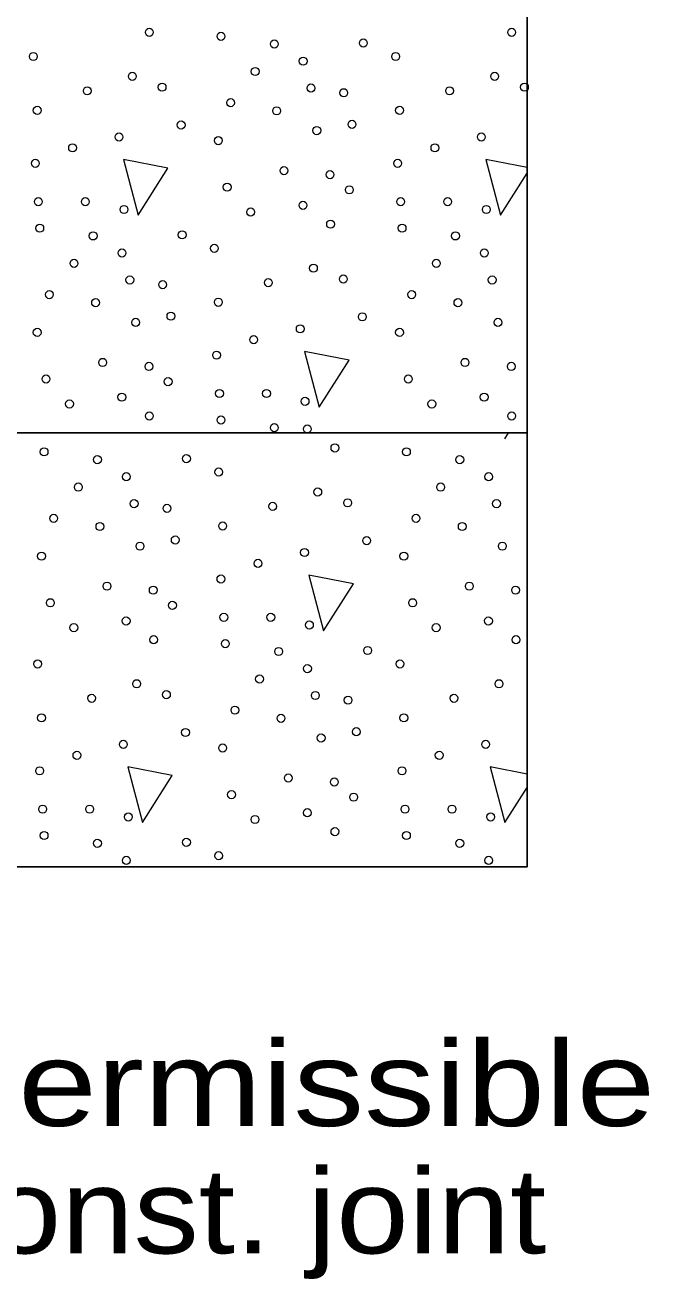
# Model space of a CAD drawing. Extents: x -410.5 to -376.5, y 1617.6 to 1661.6.
# Drawn here: x -391.077 to -389.927, y 1629.387 to 1631.696 of the extents above; entities that cross this region are included whole.
import ezdxf

# ---------------------------------------------------------------- set-up
doc = ezdxf.new("R2010")
doc.units = 0
doc.header["$LTSCALE"] = 0.062
doc.layers.add('1', color=7, linetype='Continuous', lineweight=13)

msp = doc.modelspace()

# ---------------------------------------------------------------- linework, layer by layer
at = {"layer": '1'}
for p, q in [((-390.22783, 1631.44833), (-390.20083, 1631.34592)), ((-390.15158, 1631.4335), (-390.22783, 1631.44833)), ((-390.20083, 1631.34592), (-390.15158, 1631.42333)), ((-390.19292, 1630.93383), (-390.18583, 1630.94508)), ((-390.21983, 1630.3295), (-390.19292, 1630.22717)), ((-390.15175, 1630.31625), (-390.21983, 1630.3295)), ((-390.19292, 1630.22717), (-390.15167, 1630.29192))]:
    msp.add_line(p, q, dxfattribs=at)
at = {"layer": '1', "lineweight": 25}
for points in [[(-391.09567, 1634.05167), (-391.07275, 1634.05717), (-390.86258, 1634.005), (-390.75258, 1634.02892), (-390.70333, 1634.03392), (-390.53658, 1634.02533), (-390.38608, 1633.99358), (-390.15167, 1634.0215), (-390.15167, 1630.94508), (-391.09567, 1630.94508)], [(-395.15925, 1630.79517), (-394.77725, 1630.79517), (-394.77725, 1630.1455), (-390.15167, 1630.1455), (-390.15167, 1630.94508), (-394.16367, 1630.94508), (-394.16367, 1630.79517), (-393.83325, 1630.79517), (-393.83325, 1630.64525), (-394.27908, 1630.64525), (-394.54583, 1630.79517), (-394.77725, 1630.79517)]]:
    msp.add_lwpolyline(points, dxfattribs=at)
at = {"layer": '1'}
for points in [[(-390.89542, 1631.44833), (-390.86842, 1631.34592), (-390.81342, 1631.43233)], [(-390.56158, 1631.095), (-390.53458, 1630.9925), (-390.47967, 1631.079)], [(-390.55358, 1630.68292), (-390.52667, 1630.58042), (-390.47167, 1630.66692)], [(-390.88733, 1630.3295), (-390.86033, 1630.22717), (-390.8055, 1630.31358)]]:
    msp.add_lwpolyline(points, close=True, dxfattribs=at)
for centre, major_axis in [((-390.8475, 1631.68266), (0, -0.00756)), ((-390.18, 1631.68266), (0, -0.00756)), ((-390.71567, 1631.67536), (0, -0.00756)), ((-390.61738, 1631.66105), (0, 0.00756)), ((-390.4534, 1631.66293), (0, -0.00756)), ((-391.06144, 1631.63814), (0, -0.00756)), ((-390.39393, 1631.63814), (0, -0.00756)), ((-390.65259, 1631.61046), (0, 0.00756)), ((-390.56426, 1631.62954), (0, 0.00756)), ((-390.87904, 1631.60157), (0, -0.00756)), ((-390.21154, 1631.60157), (0, -0.00756)), ((-390.96198, 1631.57489), (0, -0.00756)), ((-390.82409, 1631.58154), (0, -0.00756)), ((-390.5498, 1631.57995), (0, 0.00756)), ((-390.48944, 1631.5713), (0, -0.00756)), ((-390.29447, 1631.57489), (0, -0.00756)), ((-390.15658, 1631.58154), (0, -0.00756)), ((-390.69793, 1631.55292), (0, 0.00756)), ((-391.05421, 1631.53885), (0, -0.00756)), ((-390.61293, 1631.53796), (0, 0.00756)), ((-390.3867, 1631.53885), (0, -0.00756)), ((-390.78899, 1631.51187), (0, 0.00756)), ((-390.53906, 1631.50169), (0, 0.00756)), ((-390.47414, 1631.51317), (0, -0.00756)), ((-390.90341, 1631.48991), (0, -0.00756)), ((-390.72046, 1631.48325), (0, 0.00756)), ((-390.2359, 1631.48991), (0, -0.00756)), ((-390.98907, 1631.46989), (0, -0.00756)), ((-390.32156, 1631.46989), (0, -0.00756)), ((-391.05749, 1631.44126), (0, -0.00756)), ((-390.59969, 1631.42795), (0, 0.00756)), ((-390.38998, 1631.44126), (0, -0.00756)), ((-390.51464, 1631.42059), (0, 0.00756)), ((-390.70421, 1631.39739), (0, 0.00756)), ((-390.47921, 1631.39262), (0, -0.00756)), ((-391.0521, 1631.37065), (0, -0.00756)), ((-390.96554, 1631.37065), (0, 0.00756)), ((-390.8944, 1631.35634), (0, -0.00756)), ((-390.56454, 1631.364), (0, 0.00756)), ((-390.38459, 1631.37065), (0, -0.00756)), ((-390.29803, 1631.37065), (0, 0.00756)), ((-390.22689, 1631.35634), (0, -0.00756)), ((-390.66094, 1631.35157), (0, 0.00756)), ((-391.04943, 1631.32201), (0, -0.00756)), ((-390.78715, 1631.30958), (0, -0.00756)), ((-390.51375, 1631.32931), (0, -0.00756)), ((-390.38192, 1631.32201), (0, -0.00756)), ((-390.95113, 1631.3077), (0, 0.00756)), ((-390.28363, 1631.3077), (0, 0.00756)), ((-390.89801, 1631.27619), (0, 0.00756)), ((-390.72769, 1631.28479), (0, -0.00756)), ((-390.2305, 1631.27619), (0, 0.00756)), ((-390.98635, 1631.25711), (0, 0.00756)), ((-390.54529, 1631.24822), (0, -0.00756)), ((-390.31884, 1631.25711), (0, 0.00756)), ((-390.88355, 1631.2266), (0, 0.00756)), ((-390.8232, 1631.21795), (0, -0.00756)), ((-390.62823, 1631.22154), (0, -0.00756)), ((-390.49033, 1631.22819), (0, -0.00756)), ((-390.21604, 1631.2266), (0, 0.00756)), ((-391.03168, 1631.19957), (0, 0.00756)), ((-390.36417, 1631.19957), (0, 0.00756)), ((-390.94668, 1631.18461), (0, 0.00756)), ((-390.72046, 1631.1855), (0, -0.00756)), ((-390.27918, 1631.18461), (0, 0.00756)), ((-390.87281, 1631.14834), (0, 0.00756)), ((-390.8079, 1631.15982), (0, -0.00756)), ((-390.45523, 1631.15853), (0, 0.00756)), ((-390.20531, 1631.14834), (0, 0.00756)), ((-391.05421, 1631.1299), (0, 0.00756)), ((-390.56965, 1631.13656), (0, -0.00756)), ((-390.3867, 1631.1299), (0, 0.00756)), ((-390.65532, 1631.11654), (0, -0.00756)), ((-390.72374, 1631.08791), (0, -0.00756)), ((-390.93345, 1631.0746), (0, 0.00756)), ((-390.84839, 1631.06724), (0, 0.00756)), ((-390.26594, 1631.0746), (0, 0.00756)), ((-390.18089, 1631.06724), (0, 0.00756)), ((-391.03797, 1631.04404), (0, 0.00756)), ((-390.81296, 1631.03927), (0, -0.00756)), ((-390.37046, 1631.04404), (0, 0.00756)), ((-390.89829, 1631.01065), (0, 0.00756)), ((-390.71834, 1631.0173), (0, -0.00756)), ((-390.63179, 1631.0173), (0, 0.00756)), ((-390.23078, 1631.01065), (0, 0.00756)), ((-390.99469, 1630.99822), (0, 0.00756)), ((-390.56064, 1631.00299), (0, -0.00756)), ((-390.32718, 1630.99822), (0, 0.00756)), ((-390.8475, 1630.97596), (0, -0.00756)), ((-390.71567, 1630.96866), (0, -0.00756)), ((-390.18, 1630.97596), (0, -0.00756)), ((-390.61738, 1630.95435), (0, 0.00756)), ((-390.55656, 1630.95188), (0, 0.00756)), ((-390.50577, 1630.91719), (0, -0.00756)), ((-391.04145, 1630.90989), (0, -0.00756)), ((-390.94316, 1630.89558), (0, 0.00756)), ((-390.77917, 1630.89746), (0, -0.00756)), ((-390.37394, 1630.90989), (0, -0.00756)), ((-390.27565, 1630.89558), (0, 0.00756)), ((-390.71971, 1630.87267), (0, -0.00756)), ((-390.89004, 1630.86407), (0, 0.00756)), ((-390.22253, 1630.86407), (0, 0.00756)), ((-390.97837, 1630.84499), (0, 0.00756)), ((-390.53731, 1630.83609), (0, -0.00756)), ((-390.31086, 1630.84499), (0, 0.00756)), ((-390.87557, 1630.81448), (0, 0.00756)), ((-390.81522, 1630.80582), (0, -0.00756)), ((-390.62025, 1630.80942), (0, -0.00756)), ((-390.48235, 1630.81607), (0, -0.00756)), ((-390.20806, 1630.81448), (0, 0.00756)), ((-391.0237, 1630.78745), (0, 0.00756)), ((-390.3562, 1630.78745), (0, 0.00756)), ((-390.93871, 1630.77249), (0, 0.00756)), ((-390.71248, 1630.77338), (0, -0.00756)), ((-390.2712, 1630.77249), (0, 0.00756)), ((-390.86484, 1630.73621), (0, 0.00756)), ((-390.79992, 1630.7477), (0, -0.00756)), ((-390.44725, 1630.7464), (0, 0.00756)), ((-390.19733, 1630.73621), (0, 0.00756)), ((-391.04623, 1630.71778), (0, 0.00756)), ((-390.56168, 1630.72444), (0, -0.00756)), ((-390.37872, 1630.71778), (0, 0.00756)), ((-390.64734, 1630.70441), (0, -0.00756)), ((-390.71576, 1630.67579), (0, -0.00756)), ((-390.92547, 1630.66248), (0, 0.00756)), ((-390.84042, 1630.65512), (0, 0.00756)), ((-390.25796, 1630.66248), (0, 0.00756)), ((-390.17291, 1630.65512), (0, 0.00756)), ((-391.02999, 1630.63192), (0, 0.00756)), ((-390.80498, 1630.62715), (0, -0.00756)), ((-390.36248, 1630.63192), (0, 0.00756)), ((-390.89031, 1630.59853), (0, 0.00756)), ((-390.71036, 1630.60518), (0, -0.00756)), ((-390.62381, 1630.60518), (0, 0.00756)), ((-390.22281, 1630.59853), (0, 0.00756)), ((-390.98671, 1630.5861), (0, 0.00756)), ((-390.55267, 1630.59087), (0, -0.00756)), ((-390.3192, 1630.5861), (0, 0.00756)), ((-390.83953, 1630.56384), (0, -0.00756)), ((-390.70769, 1630.55654), (0, -0.00756)), ((-390.17202, 1630.56384), (0, -0.00756)), ((-390.6094, 1630.54223), (0, 0.00756)), ((-390.44542, 1630.54411), (0, -0.00756)), ((-391.05346, 1630.51932), (0, -0.00756)), ((-390.55628, 1630.51072), (0, 0.00756)), ((-390.38596, 1630.51932), (0, -0.00756)), ((-390.87107, 1630.48274), (0, -0.00756)), ((-390.64461, 1630.49164), (0, 0.00756)), ((-390.20356, 1630.48274), (0, -0.00756)), ((-390.95401, 1630.45607), (0, -0.00756)), ((-390.81611, 1630.46272), (0, -0.00756)), ((-390.54182, 1630.46113), (0, 0.00756)), ((-390.2865, 1630.45607), (0, -0.00756)), ((-390.68995, 1630.4341), (0, 0.00756)), ((-390.48146, 1630.45247), (0, -0.00756)), ((-391.04623, 1630.42003), (0, -0.00756)), ((-390.60495, 1630.41914), (0, 0.00756)), ((-390.37872, 1630.42003), (0, -0.00756)), ((-390.78101, 1630.39305), (0, 0.00756)), ((-390.46617, 1630.39435), (0, -0.00756)), ((-390.89543, 1630.37109), (0, -0.00756)), ((-390.71248, 1630.36443), (0, 0.00756)), ((-390.53108, 1630.38286), (0, 0.00756)), ((-390.22792, 1630.37109), (0, -0.00756)), ((-390.98109, 1630.35106), (0, -0.00756)), ((-390.31359, 1630.35106), (0, -0.00756)), ((-391.04951, 1630.32244), (0, -0.00756)), ((-390.38201, 1630.32244), (0, -0.00756)), ((-390.59171, 1630.30913), (0, 0.00756)), ((-390.50666, 1630.30177), (0, 0.00756)), ((-390.69624, 1630.27857), (0, 0.00756)), ((-390.47123, 1630.2738), (0, -0.00756)), ((-391.04412, 1630.25183), (0, -0.00756)), ((-390.95757, 1630.25183), (0, 0.00756)), ((-390.37661, 1630.25183), (0, -0.00756)), ((-390.29006, 1630.25183), (0, 0.00756)), ((-390.88642, 1630.23752), (0, -0.00756)), ((-390.65296, 1630.23275), (0, 0.00756)), ((-390.55656, 1630.24518), (0, 0.00756)), ((-390.21891, 1630.23752), (0, -0.00756)), ((-391.04145, 1630.20319), (0, -0.00756)), ((-390.50577, 1630.21049), (0, -0.00756)), ((-390.37394, 1630.20319), (0, -0.00756)), ((-390.94316, 1630.18888), (0, 0.00756)), ((-390.77917, 1630.19076), (0, -0.00756)), ((-390.27565, 1630.18888), (0, 0.00756)), ((-390.89004, 1630.15737), (0, 0.00756)), ((-390.71971, 1630.16597), (0, -0.00756)), ((-390.22253, 1630.15737), (0, 0.00756))]:
    msp.add_ellipse(centre, major_axis=major_axis, ratio=0.944543, dxfattribs=at)

# ---------------------------------------------------------------- texts
for s, width, p in [('Permissible', 1.25, (-391.26325, 1629.66825)), ('const. joint', 1.15, (-391.26325, 1629.43358))]:
    msp.add_text(s, height=0.156, dxfattribs=dict(at, width=width)).set_placement(p)

doc.saveas('drawing.dxf')
